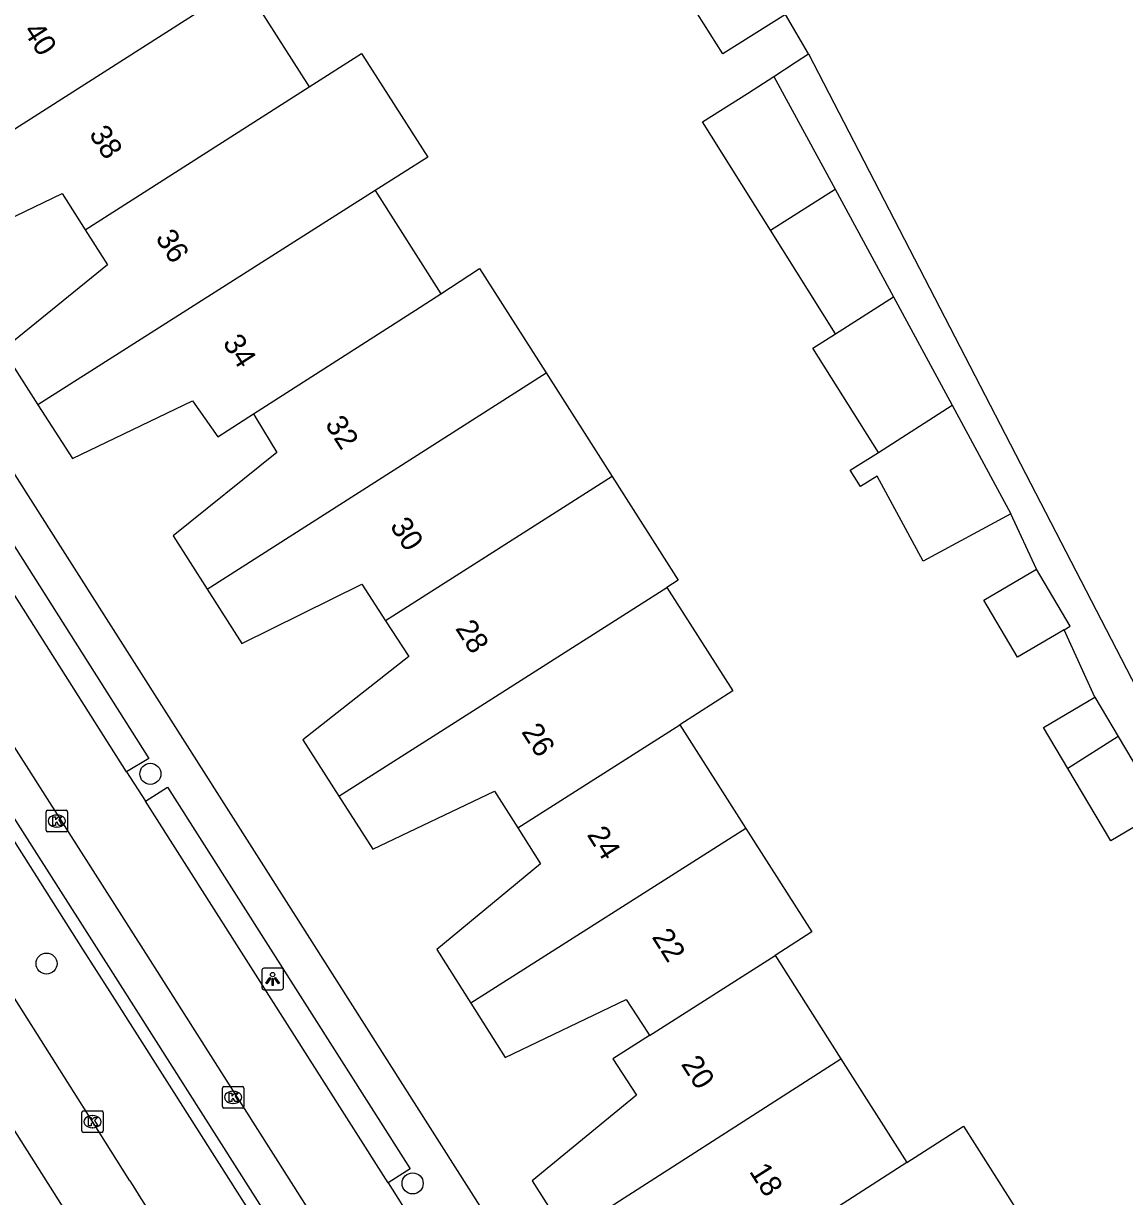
# Model space of a CAD drawing. Extents: x 159689 to 160786, y 387323 to 388339.
# Drawn here: x 159890.7 to 159941.8, y 387617.6 to 387672 of the extents above; entities that cross this region are included whole.
import ezdxf

# ---------------------------------------------------------------- set-up
doc = ezdxf.new("R2010")
doc.units = 0
for name, color, linetype in [('IMGEO_Boom', 7, 'Continuous'), ('IMGEO_Erf', 7, 'Continuous'), ('IMGEO_Fietspad_gesloten', 7, 'Continuous'), ('IMGEO_Kolk', 7, 'Continuous'), ('IMGEO_Lichtpunt', 7, 'Continuous'), ('IMGEO_OVBaan_gesloten', 7, 'Continuous'), ('IMGEO_Pand', 7, 'Continuous'), ('IMGEO_Pand_nummerreeks', 7, 'Continuous'), ('IMGEO_Rijbaan_regionaal_gesloten', 7, 'Continuous'), ('IMGEO_Voetpad_open', 7, 'Continuous')]:
    doc.layers.add(name, color=color, linetype=linetype)

msp = doc.modelspace()

# ---------------------------------------------------------------- linework, layer by layer
at = {"layer": 'IMGEO_Boom'}
for centre in [(159896.561, 387637.224), (159891.742, 387628.417), (159908.728, 387618.214)]:
    msp.add_circle(centre, 0.489, dxfattribs=at)
at = {"layer": 'IMGEO_Erf'}
msp.add_lwpolyline([(159927.099, 387670.64), (159926.035, 387672.47)], dxfattribs=at)
at = {"layer": 'IMGEO_Fietspad_gesloten'}
for points in [[(159858.565, 387688.232), (159871.375, 387668.071), (159896.663, 387628.381), (159918.222, 387594.432), (159932.893, 387571.356)], [(159895.454, 387637.315), (159883.934, 387655.5)], [(159895.454, 387637.315), (159896.34, 387635.958)], [(159907.589, 387618.24), (159896.34, 387635.958)], [(159907.589, 387618.24), (159908.409, 387616.936)]]:
    msp.add_lwpolyline(points, dxfattribs=at)
at = {"layer": 'IMGEO_Kolk'}
for p, q in [((159891.793, 387635.532), (159892.645, 387635.532)), ((159891.718, 387634.606), (159891.718, 387635.458)), ((159892.206, 387635.312), (159892.231, 387635.312)), ((159892.719, 387635.458), (159892.719, 387634.606)), ((159892.645, 387634.532), (159891.793, 387634.532)), ((159892.229, 387634.752), (159892.204, 387634.752)), ((159899.9, 387621.782), (159899.9, 387622.634)), ((159899.975, 387622.708), (159900.827, 387622.708)), ((159900.388, 387622.488), (159900.413, 387622.488)), ((159900.901, 387622.634), (159900.901, 387621.782)), ((159900.411, 387621.928), (159900.386, 387621.928)), ((159893.375, 387620.653), (159893.375, 387621.505)), ((159893.45, 387621.579), (159894.302, 387621.579)), ((159893.863, 387621.359), (159893.888, 387621.359)), ((159894.376, 387621.505), (159894.376, 387620.653)), ((159900.827, 387621.708), (159899.975, 387621.708)), ((159893.886, 387620.799), (159893.861, 387620.799)), ((159894.302, 387620.579), (159893.45, 387620.579))]:
    msp.add_line(p, q, dxfattribs=at)
for points in [[(159891.793, 387635.532), (159892.645, 387635.532)], [(159891.718, 387634.606), (159891.718, 387635.458)], [(159892.039, 387635.232), (159892.162, 387635.232), (159892.162, 387635.081), (159892.292, 387635.232), (159892.456, 387635.232), (159892.31, 387635.081), (159892.463, 387634.832), (159892.311, 387634.832), (159892.226, 387634.996), (159892.162, 387634.929), (159892.162, 387634.832), (159892.039, 387634.832), (159892.039, 387635.232)], [(159892.719, 387635.458), (159892.719, 387634.606)], [(159892.645, 387634.532), (159891.793, 387634.532)], [(159899.9, 387621.782), (159899.9, 387622.634)], [(159899.975, 387622.708), (159900.827, 387622.708)], [(159900.221, 387622.408), (159900.344, 387622.408), (159900.344, 387622.257), (159900.474, 387622.408), (159900.638, 387622.408), (159900.492, 387622.257), (159900.645, 387622.008), (159900.493, 387622.008), (159900.408, 387622.172), (159900.344, 387622.105), (159900.344, 387622.008), (159900.221, 387622.008), (159900.221, 387622.408)], [(159900.901, 387622.634), (159900.901, 387621.782)], [(159893.375, 387620.653), (159893.375, 387621.505)], [(159893.45, 387621.579), (159894.302, 387621.579)], [(159894.376, 387621.505), (159894.376, 387620.653)], [(159900.827, 387621.708), (159899.975, 387621.708)], [(159893.696, 387621.279), (159893.819, 387621.279), (159893.819, 387621.128), (159893.949, 387621.279), (159894.113, 387621.279), (159893.967, 387621.128), (159894.12, 387620.879), (159893.968, 387620.879), (159893.883, 387621.043), (159893.819, 387620.976), (159893.819, 387620.879), (159893.696, 387620.879), (159893.696, 387621.279)], [(159894.302, 387620.579), (159893.45, 387620.579)]]:
    msp.add_lwpolyline(points, dxfattribs=at)
for centre, start, end in [((159891.795, 387635.456), 91.552, 178.448), ((159891.795, 387635.456), 91.552, 178.448), ((159892.643, 387635.456), 1.552, 88.448), ((159892.643, 387635.456), 1.552, 88.448), ((159891.795, 387634.608), 181.552, 268.448), ((159891.795, 387634.608), 181.552, 268.448), ((159892.643, 387634.608), 271.552, 358.448), ((159892.643, 387634.608), 271.552, 358.448), ((159899.977, 387622.632), 91.552, 178.448), ((159899.977, 387622.632), 91.552, 178.448), ((159900.825, 387622.632), 1.552, 88.448), ((159900.825, 387622.632), 1.552, 88.448), ((159893.452, 387621.503), 91.552, 178.448), ((159893.452, 387621.503), 91.552, 178.448), ((159894.3, 387621.503), 1.552, 88.448), ((159894.3, 387621.503), 1.552, 88.448), ((159899.977, 387621.784), 181.552, 268.448), ((159899.977, 387621.784), 181.552, 268.448), ((159900.825, 387621.784), 271.552, 358.448), ((159900.825, 387621.784), 271.552, 358.448), ((159893.452, 387620.655), 181.552, 268.448), ((159893.452, 387620.655), 181.552, 268.448), ((159894.3, 387620.655), 271.552, 358.448), ((159894.3, 387620.655), 271.552, 358.448)]:
    msp.add_arc(centre, 0.0765, start, end, dxfattribs=at)
for centre, major_axis, ratio, start_param, end_param in [((159892.205, 387635.032), (-0.387, 0.002), 0.722429, 4.712389, 7.853982), ((159892.23, 387635.032), (-0.39, 0.002), 0.717154, 1.570796, 4.712389), ((159900.387, 387622.208), (-0.387, 0.002), 0.722429, 4.712389, 7.853982), ((159900.412, 387622.208), (-0.39, 0.002), 0.717154, 1.570796, 4.712389), ((159893.862, 387621.079), (-0.387, 0.002), 0.722429, 4.712389, 7.853982), ((159893.887, 387621.079), (-0.39, 0.002), 0.717154, 1.570796, 4.712389)]:
    msp.add_ellipse(centre, major_axis=major_axis, ratio=ratio, start_param=start_param, end_param=end_param, dxfattribs=at)
at = {"layer": 'IMGEO_Lichtpunt'}
for p, q in [((159901.733, 387628.106), (159901.733, 387627.299)), ((159901.733, 387628.106), (159901.733, 387627.299)), ((159902.635, 387628.201), (159901.827, 387628.201)), ((159902.635, 387628.201), (159901.827, 387628.201)), ((159902.729, 387627.299), (159902.729, 387628.106)), ((159902.729, 387627.299), (159902.729, 387628.106)), ((159901.827, 387627.205), (159902.635, 387627.205)), ((159901.827, 387627.205), (159902.635, 387627.205))]:
    msp.add_line(p, q, dxfattribs=at)
for points in [[(159902.107, 387627.77), (159902.146, 387627.742), (159901.958, 387627.48), (159901.92, 387627.507), (159902.107, 387627.77)], [(159902.209, 387627.722), (159902.256, 387627.722), (159902.256, 387627.4), (159902.209, 387627.4), (159902.209, 387627.722)], [(159902.319, 387627.742), (159902.357, 387627.769), (159902.544, 387627.507), (159902.505, 387627.479), (159902.319, 387627.742)]]:
    msp.add_lwpolyline(points, dxfattribs=at)
msp.add_circle((159902.232, 387627.904), 0.0994, dxfattribs=at)
for centre, start, end in [((159901.827, 387628.106), 90, 180), ((159901.827, 387628.106), 90, 180), ((159902.635, 387628.106), 0, 90), ((159902.635, 387628.106), 0, 90), ((159901.827, 387627.299), 180, 270), ((159901.827, 387627.299), 180, 270), ((159902.635, 387627.299), 270, 0), ((159902.635, 387627.299), 270, 360)]:
    msp.add_arc(centre, 0.0946, start, end, dxfattribs=at)
at = {"layer": 'IMGEO_OVBaan_gesloten'}
msp.add_lwpolyline([(159869.099, 387654.066), (159900.012, 387605.234)], dxfattribs=at)
at = {"layer": 'IMGEO_Pand'}
for points in [[(159900.864, 387673.918), (159885.255, 387663.953)], [(159900.864, 387673.918), (159903.926, 387669.11)], [(159926.035, 387672.47), (159923.115, 387670.637), (159921.354, 387673.443)], [(159903.926, 387669.11), (159906.357, 387670.662), (159909.427, 387665.842), (159906.992, 387664.295)], [(159925.331, 387662.455), (159922.178, 387667.48), (159924.272, 387668.794), (159925.494, 387669.594)], [(159925.494, 387669.594), (159928.327, 387664.363)], [(159893.533, 387662.473), (159903.926, 387669.11)], [(159925.331, 387662.455), (159928.327, 387664.363)], [(159928.327, 387664.363), (159931.038, 387659.356)], [(159885.255, 387663.953), (159886.863, 387661.467), (159892.467, 387664.154), (159893.533, 387662.473)], [(159906.992, 387664.295), (159891.343, 387654.352)], [(159906.992, 387664.295), (159910.041, 387659.505)], [(159893.533, 387662.473), (159894.563, 387660.849), (159889.712, 387656.9), (159891.343, 387654.352)], [(159928.352, 387657.641), (159925.331, 387662.455)], [(159910.041, 387659.505), (159911.838, 387660.678), (159914.927, 387655.829)], [(159901.349, 387653.925), (159908.865, 387658.737), (159910.041, 387659.505)], [(159928.352, 387657.641), (159931.038, 387659.356)], [(159931.038, 387659.356), (159933.762, 387654.326)], [(159930.343, 387652.144), (159927.305, 387656.985), (159928.352, 387657.641)], [(159899.189, 387645.797), (159914.927, 387655.829)], [(159914.927, 387655.829), (159917.989, 387651.021)], [(159891.343, 387654.352), (159892.939, 387651.859), (159898.517, 387654.534), (159899.686, 387652.861), (159901.349, 387653.925)], [(159930.343, 387652.144), (159933.762, 387654.326)], [(159933.762, 387654.326), (159936.486, 387649.296)], [(159901.349, 387653.925), (159901.456, 387653.749), (159902.435, 387652.142), (159897.61, 387648.268), (159899.189, 387645.797)], [(159936.486, 387649.296), (159932.423, 387647.096), (159930.285, 387651.044), (159929.505, 387650.554), (159929.026, 387651.318), (159930.343, 387652.144)], [(159917.989, 387651.021), (159907.473, 387644.321)], [(159917.989, 387651.021), (159921.05, 387646.215), (159920.522, 387645.874)], [(159938.957, 387643.906), (159936.797, 387642.635), (159935.235, 387645.29), (159937.675, 387646.725)], [(159938.957, 387643.906), (159939.237, 387644.071), (159937.675, 387646.725)], [(159899.189, 387645.797), (159900.799, 387643.279), (159906.365, 387646.03), (159907.473, 387644.321)], [(159905.309, 387636.187), (159920.522, 387645.874)], [(159920.522, 387645.874), (159923.583, 387641.069), (159921.122, 387639.498)], [(159907.473, 387644.321), (159908.55, 387642.661), (159903.636, 387638.801), (159905.309, 387636.187)], [(159939.135, 387637.464), (159938.004, 387639.375), (159940.387, 387640.786)], [(159940.387, 387640.786), (159941.471, 387638.954)], [(159913.603, 387634.721), (159921.122, 387639.498)], [(159921.122, 387639.498), (159924.186, 387634.69)], [(159941.471, 387638.954), (159939.135, 387637.464)], [(159941.471, 387638.954), (159943.501, 387635.526)], [(159943.501, 387635.526), (159941.118, 387634.115), (159939.135, 387637.464)], [(159905.309, 387636.187), (159906.888, 387633.722), (159912.53, 387636.421), (159913.603, 387634.721)], [(159913.603, 387634.721), (159914.664, 387633.04), (159909.851, 387629.065), (159911.428, 387626.582)], [(159924.186, 387634.69), (159911.428, 387626.582)], [(159924.186, 387634.69), (159927.249, 387629.882), (159925.546, 387628.796)], [(159919.72, 387625.08), (159925.546, 387628.796)], [(159925.546, 387628.796), (159925.638, 387628.652), (159928.6, 387623.996)], [(159911.428, 387626.582), (159913.027, 387624.063), (159918.643, 387626.75), (159919.623, 387625.231), (159919.72, 387625.08)], [(159919.72, 387625.08), (159918.018, 387623.994), (159919.12, 387622.302), (159914.269, 387618.34), (159915.867, 387615.823)], [(159915.867, 387615.823), (159928.6, 387623.996)], [(159928.6, 387623.996), (159931.661, 387619.185)], [(159931.661, 387619.185), (159934.281, 387620.864), (159937.345, 387616.048)], [(159931.661, 387619.185), (159924.147, 387614.348)]]:
    msp.add_lwpolyline(points, dxfattribs=at)
at = {"layer": 'IMGEO_Rijbaan_regionaal_gesloten'}
msp.add_lwpolyline([(159895.607, 387618.335), (159893.876, 387621.079), (159881.358, 387640.862), (159870.936, 387657.259), (159862.656, 387670.301), (159859.345, 387675.48), (159854.91, 387682.508), (159848.808, 387692.139), (159844.283, 387699.312), (159843.801, 387700.086), (159843.321, 387700.86)], dxfattribs=at)
msp.add_arc((159961.627, 387659.076), 77.579, 211.67861, 221.3213, dxfattribs=at)
at = {"layer": 'IMGEO_Voetpad_open'}
for points in [[(159925.947, 387595.016), (159925.086, 387596.373), (159913.458, 387614.655), (159903.748, 387629.93), (159892.284, 387647.962), (159880.486, 387666.503), (159871.272, 387681.013), (159866.365, 387688.698), (159861.884, 387695.822), (159856.385, 387704.612), (159855.275, 387706.413), (159852.398, 387711.107)], [(159915.314, 387592.825), (159916.154, 387593.379), (159913.887, 387596.942), (159902.311, 387615.135), (159894.697, 387627.102), (159893.433, 387629.088), (159887.557, 387638.32), (159869.453, 387666.765), (159856.552, 387687.024), (159856.448, 387687.183), (159856.345, 387687.342)], [(159930.011, 387572.581), (159916.611, 387593.674), (159895.175, 387627.432), (159869.914, 387667.073), (159857.025, 387687.322), (159856.897, 387687.521), (159856.768, 387687.721)], [(159925.494, 387669.594), (159926.53, 387670.269), (159927.099, 387670.64)], [(159927.099, 387670.64), (159953.086, 387620.379)], [(159883.934, 387655.5), (159884.972, 387656.109), (159896.483, 387637.94), (159895.454, 387637.315)], [(159937.675, 387646.725), (159936.486, 387649.296)], [(159940.387, 387640.786), (159938.957, 387643.906)], [(159896.34, 387635.958), (159897.351, 387636.611), (159908.618, 387618.883), (159907.589, 387618.24)]]:
    msp.add_lwpolyline(points, dxfattribs=at)

# ---------------------------------------------------------------- texts
at = {"layer": 'IMGEO_Pand_nummerreeks'}
for s, rotation, p in [('40', 302.5126, (159890.635, 387671.709)), ('38', 302.5126, (159893.689, 387666.917)), ('36', 302.6469, (159896.769, 387662.094)), ('34', 302.6469, (159899.889, 387657.224)), ('32', 302.5495, (159904.638, 387653.446)), ('30', 302.5479, (159907.649, 387648.728)), ('28', 302.5583, (159910.686, 387643.972)), ('26', 302.5583, (159913.75, 387639.174)), ('24', 302.3891, (159916.793, 387634.396)), ('22', 302.3891, (159919.802, 387629.653)), ('20', 302.4464, (159921.158, 387623.749)), ('18', 302.4455, (159924.323, 387618.769))]:
    msp.add_text(s, height=1, rotation=rotation, dxfattribs=at).set_placement(p)

doc.saveas('drawing.dxf')
